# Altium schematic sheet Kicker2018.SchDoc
size A4
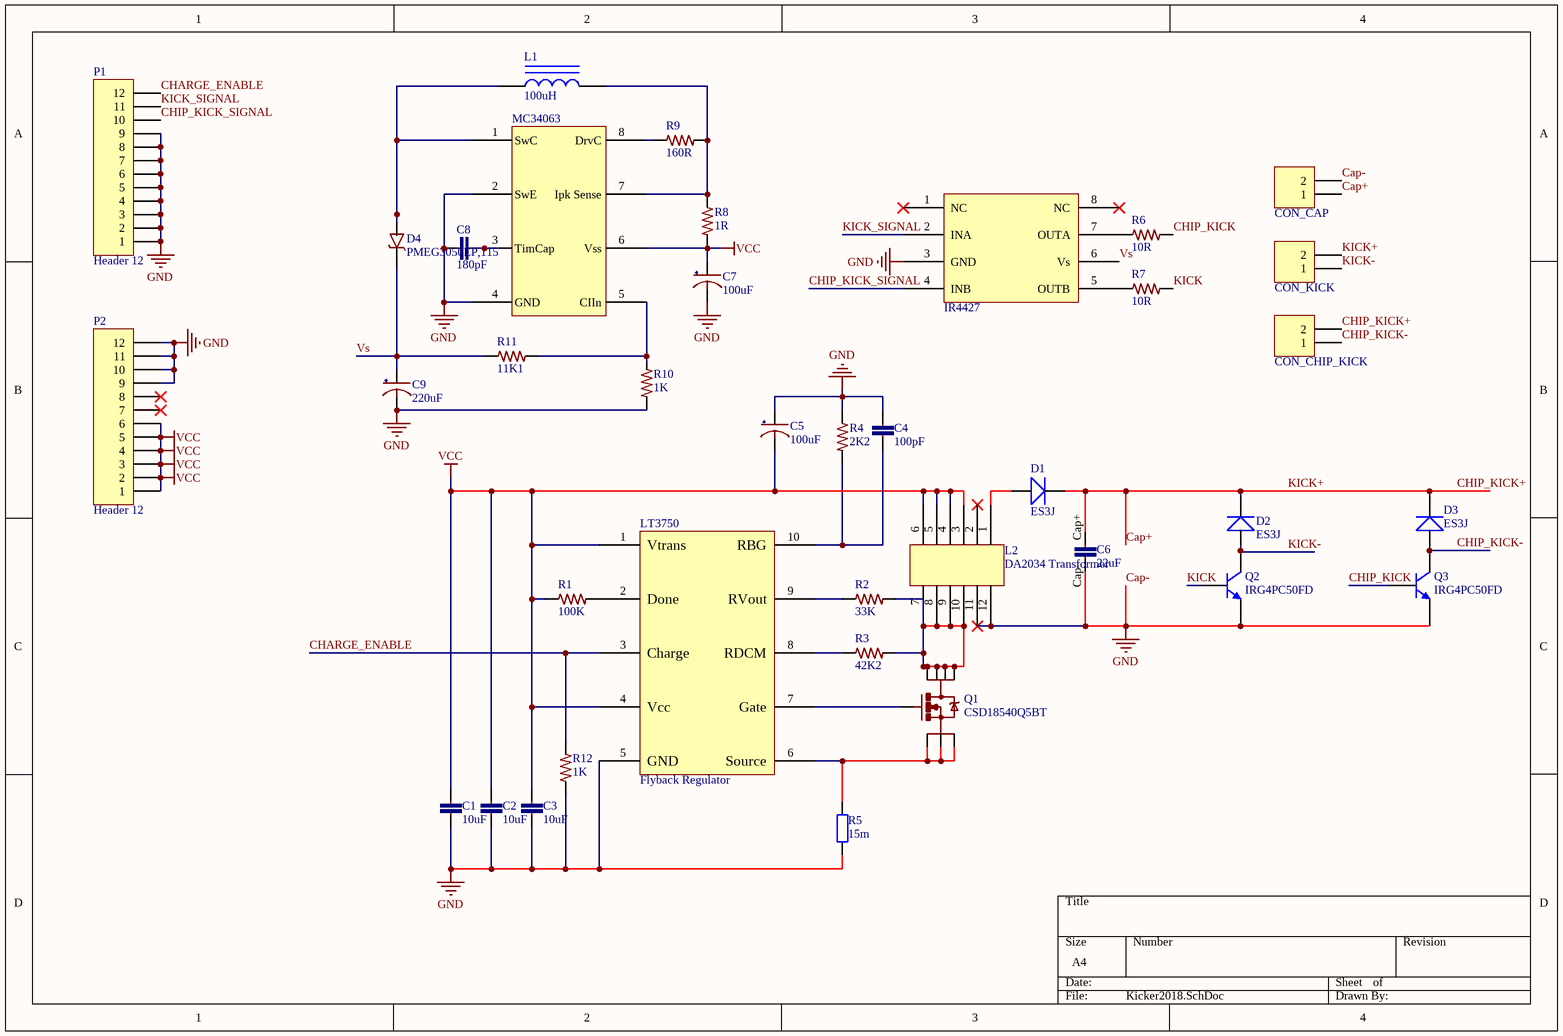
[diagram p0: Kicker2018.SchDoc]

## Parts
C1  10uF  [CAPC0603(1608)55_L]
C2  10uF  [CAPC0603(1608)55_L]
C3  10uF  [CAPC0603(1608)55_L]
C4  100pF  [CAPC0603(1608)55_L]
C5  100uF  [PCBComponent]
C6  22uF  [CAP ALUM 22UF 250V]
C7  100uF  [7343-CAPPOL]
C8  180pF  [0805-CAP]
C9  220uF  [NIC-CAPA2-10X10_V]
CON_CAP  OSTTA024163  [Term Block 2P]  (value not drawn)
CON_CHIP_KICK  OSTTA024163  [Term Block 2P]  (value not drawn)
CON_KICK  OSTTA024163  [Term Block 2P]  (value not drawn)
D1  ES3J  [Diode]
D2  ES3J  [Diode]
D3  ES3J  [Diode]
D4  PMEG3050EP,115  [PCBComponent]
IR4427  GATE DRIVER  [IR4427]  (value not drawn)
L1  100uH  [INDUCTOR]
L2  DA2034 Transformer  [DA2034 Transformer]
LT3750  Flyback Regulator  [LT3750]
MC34063  Switching Voltage Regulator  [MC34063]  (value not drawn)
P1  Header 12  [HDR1X12]
P2  Header 12  [HDR1X12]
Q1  CSD18540Q5BT  [PCBComponent]
Q2  IRG4PC50FD  [IRG4PC50FD]
Q3  IRG4PC50FD  [IRG4PC50FD]
R1  100K  [0402-RES-HD]
R2  33K  [0402-RES-HD]
R3  42K2  [0402-RES-HD]
R4  2K2  [0402-RES-HD]
R5  15m  [RES1206]
R6  10R  [0402-RES-HD]
R7  10R  [0402-RES-HD]
R8  1R  [0805-RES]
R9  160R  [0805-RES]
R10  1K  [0402-RES-HD]
R11  11K1  [0402-RES-HD]
R12  1K  [0402-RES-HD]

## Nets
Cap-: C1.2 C2.2 C3.2 C4.1 C5.1(+) C6.Cap- C7.2(-) C8.1 C9.2(-) CON_CAP.2 IR4427.3(GND) L2.11 L2.12 LT3750.5(GND) MC34063.2(SwE) MC34063.4(GND) P1.1 P1.2 P1.3 P1.4 P1.5 P1.6 P1.7 P1.8 P1.9 P2.9 P2.10 P2.11 P2.12 Q2.3(E) Q3.3(E) R4.2 R5.2 R10.1 R12.1  [also labelled GND]
VCC: C1.1 C2.1 C3.1 C5.2(-) C7.1(+) L2.3 L2.4 L2.5 L2.6 LT3750.1(Vtrans) LT3750.4(Vcc) MC34063.6(Vss) P2.1 P2.2 P2.3 P2.4 P2.5 P2.6 R1.1 R8.1
Cap+: C6.Cap+ CON_CAP.1 CON_CHIP_KICK.2 CON_KICK.2 D1.D1+ D2.D1+ D3.D1+  [also labelled CHIP_KICK+, KICK+]
CHARGE_ENABLE: LT3750.3(Charge) P1.12 R12.2
CHIP_KICK: Q3.2(G) R6.2
CHIP_KICK-: CON_CHIP_KICK.1 D3.D1- Q3.1(C)
CHIP_KICK_SIGNAL: IR4427.4(INB) P1.10
KICK: Q2.2(G) R7.2
KICK-: CON_KICK.1 D2.D1- Q2.1(C)
KICK_SIGNAL: IR4427.2(INA) P1.11
Vs: C9.1(+) D4.1(C) IR4427.6(Vs) R11.1
NetC4_2: C4.2 LT3750.10(RBG) R4.1
NetC8_2: C8.2 MC34063.3(TimCap)
NetD1_D1-: D1.D1- L2.1
NetD4_2: D4.2(A) L1.1 MC34063.1(SwC)
NetIR4427_5: IR4427.5(OUTB) R7.1
NetIR4427_7: IR4427.7(OUTA) R6.1
NetL1_2: L1.2 MC34063.7(Ipk_Sense) R8.2 R9.2
NetL2_7: L2.7 L2.8 L2.9 L2.10 Q1.5(D) Q1.6(D) Q1.7(D) Q1.8(D) R2.2 R3.2
NetLT3750_2: LT3750.2(Done) R1.2
NetLT3750_6: LT3750.6(Source) Q1.1(S) Q1.2(S) Q1.3(S) R5.1
NetLT3750_7: LT3750.7(Gate) Q1.4(G)
NetLT3750_8: LT3750.8(RDCM) R3.1
NetLT3750_9: LT3750.9(RVout) R2.1
NetMC34063_5: MC34063.5(CIIn) R10.2 R11.2
NetMC34063_8: MC34063.8(DrvC) R9.1

Not connected (* = marked no-connect by the designer): IR4427 1(NC)* 8(NC)*; L2 2*; P2 7* 8*

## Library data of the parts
C1-C3 = C0603-10uF-16V-1: CAP CER 10UF 16V X5R 0603; Part No: EMK107BBJ106MA-T; Cod EMS: 05.281.019.592
C4 = CC0603--1: CAP CER 100PF 50V NP0 0603; Part No: GRM1885C1H101JA01D
C5 = CA-100uF-3: CAP ALUM 100UF 20% 80V SMD
C6 = CAP ALUM 22UF 250V
C7 = CT2917-100uF-1: CAP TANT 100uF 25V 20% ESR = 30mOhm @ 100 kHz; Part No: T521X107M025ATE030
C8 = CC0805-180pF-2: CAP CER 180PF 50V NP0 0805; Part No: C0805C181K5GACTU; Cod EMS: 05.281.019.399
C9 = CA-220uF-1: CAP ALUM 220uF 20% 50V  ESR = 0,18 ohms  Radial DIA 10mm HEIGH 10,2mm; Part No: EEEFK1H221P; Cod EMS: 05.281.030.094
CON_CAP CON_CHIP_KICK CON_KICK = Term Block 2P: 2 Position Wire to Board Terminal Block Horizontal with Board 0.200" (5.08mm) Through Hole
D4 = PMEG3050EP,115-01.A.5: DIODE SCHOTTKY 30V 5A SOD128; Cod EMS: 05.284.051.031
IR4427 = IR4427: IC DRIVER DUAL LOW SIDE 8-SOIC
L1 = Inductor: Fixed Inductors 100uH 0.86A SMT
LT3750 = LT3750
MC34063 = MC34063
P1 P2 = Header 12: Header, 12-Pin
Q1 = CSD18540Q5BT-1: MOSFET N-CH 60V 100A 8VSON
Q2 Q3 = IRG4PC50FD: IGBT Transistors 600V FAST 1-8 KHZ COPACK IGBT
R1 = R0402-100K-11: RES 100K OHM 1/10W 1% 0402 SMD 1; Part No: ERJ-2GEJ104X; Cod EMS: 05.280.029.504; Family Description: RESISTOR FILME ESPESSO 0R-1M / 1/10W / 5% /  0402. P/N: ERJ-2GE....X – PANASONIC ELECTRONIC COMPONENTS.
R2 = R0402-33K-7: RES 33K OHM 1/10W 1% 0402 SMD; Part No: ERJ-2RKF3302X; Cod EMS: 05.280.029.535; Family Description: RESISTOR FILME ESPESSO 10R-1M / 1/10W / 1% / 0402. P/N: ERJ-2RKF....X – PANASONIC ELECTRONIC COMPONENTS.
R3 = RESISTOR: RES 42.2K OHM 1/10W 1% 0402 SMD; Part No: ERJ-2RKF4222X
R4 = R0402-2K2-5: RES 2.2K OHM 1/10W 1% 0402 SMD; Part No: ERJ-2RKF2201X; Cod EMS: 05.280.029.541; Family Description: RESISTOR FILME ESPESSO 10R-1M / 1/10W / 1% / 0402. P/N: ERJ-2RKF....X – PANASONIC ELECTRONIC COMPONENTS.
R5 = Res2: Resistor
R6 R7 = R0402-10R-6: RES 10 OHM 1/10W 1% 0402 SMD; Part No: ERJ-2RKF10R0X; Cod EMS: 05.280.029.523; Value: 10; Family Description: RESISTOR FILME ESPESSO 10R-1M / 1/10W / 1% / 0402. P/N: ERJ-2RKF....X – PANASONIC ELECTRONIC COMPONENTS.
R8 = R0805-1R-1%-1: RES SMD 1 OHM 1% 1/8W 0805; Part No: CRCW08051R00FKEA; Cod EMS: 05.280.029.391
R9 = R0805-160R-5: RES 160 OHM 1/8W .5% 0805 SMD; Part No: ERA-6AED161V; Cod EMS: 05.280.029.516; Value: 160
R10 R12 = R0402-1K-A.9: RES 1K OHM 1/10W 1% 0402 SMD; Part No: ERJ-2RKF1001X; Cod EMS: 05.280.029.527; Family Description: RESISTOR FILME ESPESSO 10R-1M / 1/10W / 1% / 0402. P/N: ERJ-2RKF....X – PANASONIC ELECTRONIC COMPONENTS.
R11 = R0402-11K1-1: RES 11.1 KOHM 1/16W 0.1% 0402 SMD; Part No: TNPW040211K1BEED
